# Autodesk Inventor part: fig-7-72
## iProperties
Created: 2004-05
Part Number: fig-7-72
Document SubType Name: Modeling
Designer: CADCIM Technologies
Manufacturer: Standard
Standards Organization: Custom
Density: 1 g/cm^3
Author: CADCIM Technologies
